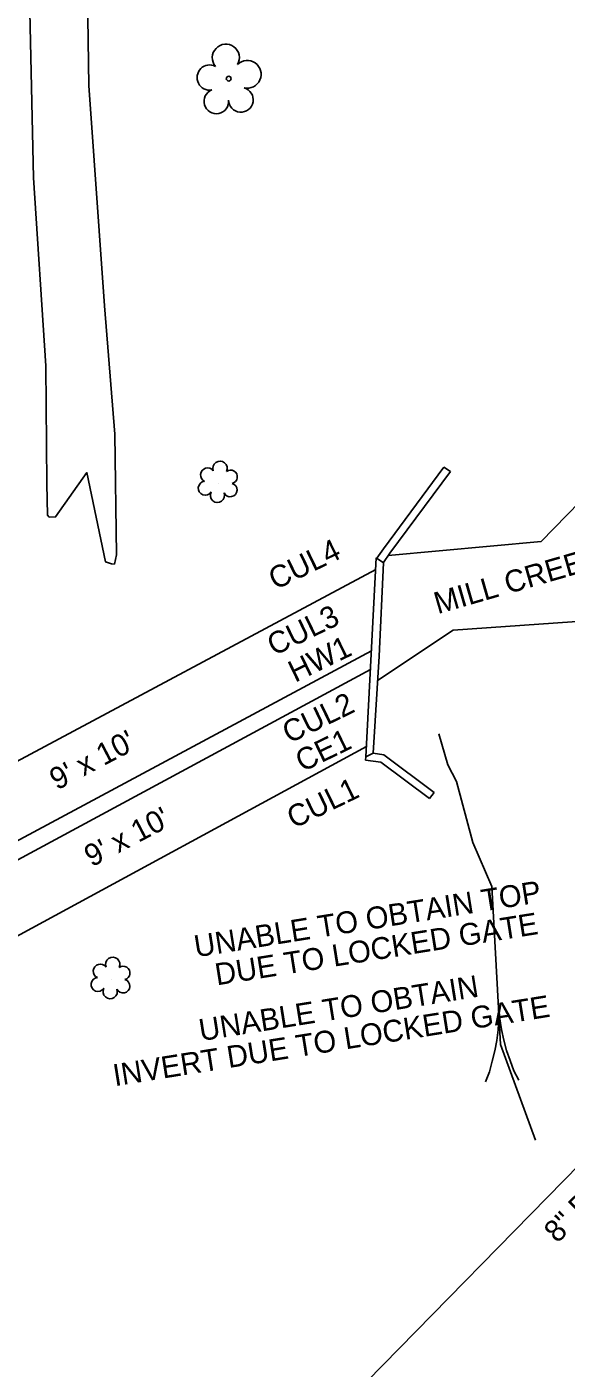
# Model space of a CAD drawing. Extents: x 1645945 to 2447332, y 713118 to 970361.
# Drawn here: x 1646352.4 to 1646426.4, y 969166.9 to 969350.8 of the extents above; entities that cross this region are included whole.
import ezdxf

# ---------------------------------------------------------------- set-up
doc = ezdxf.new("R2010")
doc.units = 0
for name, color, linetype in [('Exist Hydro Jurisdictional Stream or Body of Water', 7, 'Continuous'), ('Exist Hydro Stream Flow Arrow CELL', 7, 'Continuous'), ('Exist Hydro Stream or Body of Water', 7, 'Continuous'), ('Exist Hydro Stream or Body of Water Text', 7, 'Continuous'), ('Exist Roads EOP', 7, 'Continuous'), ('Exist Structure Major Box Culvert or Tunnel Topo', 7, 'Continuous'), ('Exist Structure Major Box Culvert or Tunnel Topo Text', 7, 'Continuous'), ('Exist Structure Major Bridge WW', 7, 'Continuous'), ('Exist Structure Major Bridge WW Text', 7, 'Continuous'), ('Exist Utilities Sanitary Sewer Manhole Top Elevation', 7, 'Continuous'), ('Exist Utilities Sanitary Sewer UG Line', 7, 'Continuous'), ('Exist Utilities Sanitary Sewer UG Line Invert Elevation', 7, 'Continuous'), ('Exist Utilities Sanitary Sewer UG Line Text', 7, 'Continuous'), ('Exist Vegetation Shrub CELL', 7, 'Continuous'), ('Exist Vegetation Tree CELL', 7, 'Continuous'), ('Exist Vegetation Woods Line', 7, 'Continuous')]:
    doc.layers.add(name, color=color, linetype=linetype)

msp = doc.modelspace()

# ---------------------------------------------------------------- linework, layer by layer
at = {"layer": 'Exist Hydro Jurisdictional Stream or Body of Water'}
for points in [[(1646401.99, 969278.32), (1646423.01, 969280.26), (1646437.23, 969294.85), (1646457.43, 969315.9), (1646475.67, 969321.15), (1646485.57, 969322.27), (1646516.72, 969316.81), (1646532.37, 969313.33), (1646530.94, 969311.42), (1646556.57, 969305.09), (1646573.02, 969284.42), (1646579.39, 969286.45), (1646594.79, 969278.15), (1646612.91, 969277.12), (1646627.6, 969287.18), (1646621.62, 969307.78), (1646603.14, 969335.3), (1646602.11, 969357.23), (1646611.25, 969365.23), (1646620.99, 969368.56)], [(1646400.54, 969261.2), (1646410.92, 969268.12), (1646429.85, 969269.44), (1646447.81, 969287.37), (1646463.87, 969298.89), (1646476.09, 969310.23), (1646484.82, 969314.47), (1646502.05, 969312.4), (1646515.09, 969307.54), (1646531.96, 969305.19), (1646552.01, 969296.08), (1646566.89, 969282.54), (1646572.86, 969281.73), (1646573.04, 969276.65), (1646593.17, 969267.28), (1646615.05, 969269.41), (1646633.01, 969284.64), (1646632.51, 969310.52), (1646631.26, 969330.1), (1646614.63, 969342.37), (1646608.88, 969351.32), (1646612.08, 969360.76), (1646623.03, 969361.26)]]:
    msp.add_lwpolyline(points, dxfattribs=at)
at = {"layer": 'Exist Hydro Stream Flow Arrow CELL'}
msp.add_line((1646417.4, 969211.26), (1646417.4, 969211.26), dxfattribs=at)
for points in [[(1646415.34, 969206.16), (1646415.88, 969207.52), (1646416.28, 969208.97), (1646416.65, 969210.4), (1646416.9, 969211.82), (1646417.08, 969213.29), (1646417.17, 969214.79), (1646417.18, 969216.25)], [(1646419.91, 969206.36), (1646419.25, 969207.67), (1646418.73, 969209.07), (1646418.23, 969210.47), (1646417.85, 969211.86), (1646417.55, 969213.31), (1646417.32, 969214.79), (1646417.18, 969216.25)]]:
    msp.add_lwpolyline(points, dxfattribs=at)
at = {"layer": 'Exist Hydro Stream or Body of Water'}
msp.add_lwpolyline([(1646422.22, 969198.15), (1646417.4, 969211.26), (1646416.21, 969232.96), (1646413.62, 969238.97), (1646411.35, 969247.33), (1646410.16, 969249.65), (1646408.93, 969253.86)], dxfattribs=at)
at = {"layer": 'Exist Roads EOP'}
msp.add_spline([(1646379.88, 969432.02), (1646359.09, 969426.37), (1646353.34, 969423.7), (1646346.05, 969418.75), (1646333.89, 969406.7), (1646326.81, 969393.02), (1646325.09, 969385.45), (1646325.5, 969379.16), (1646330.03, 969336.13), (1646333.52, 969294.46), (1646334.18, 969250.57), (1646332.28, 969209.59), (1646328.48, 969164.09), (1646321.21, 969122.91)], degree=3, dxfattribs=at)
at = {"layer": 'Exist Structure Major Box Culvert or Tunnel Topo'}
for p, q in [((1646246.39, 969194.17), (1646400.28, 969276.43)), ((1646245.55, 969182.6), (1646399.69, 969265.26)), ((1646399.55, 969262.69), (1646245.35, 969179.57)), ((1646244.67, 969168.45), (1646399, 969252.16))]:
    msp.add_line(p, q, dxfattribs=at)
at = {"layer": 'Exist Structure Major Bridge WW'}
for p, q in [((1646409.62, 969290.47), (1646410.53, 969289.87)), ((1646398.92, 969250.71), (1646400.36, 969278)), ((1646398.9, 969250.25), (1646398.92, 969250.71)), ((1646400.98, 969249.99), (1646398.9, 969250.25)), ((1646401.4, 969251.02), (1646399.93, 969251.21)), ((1646407.64, 969244.99), (1646400.98, 969249.99)), ((1646408.29, 969245.85), (1646401.4, 969251.02)), ((1646408.29, 969245.85), (1646407.64, 969244.99))]:
    msp.add_line(p, q, dxfattribs=at)
for points in [[(1646400.42, 969277.95), (1646401.33, 969279.25), (1646409.62, 969290.47)], [(1646401.34, 969277.37), (1646402.24, 969278.66), (1646410.53, 969289.87)], [(1646398.92, 969250.71), (1646399.93, 969251.21), (1646400.74, 969264.52), (1646401.37, 969277.35), (1646400.36, 969278)]]:
    msp.add_lwpolyline(points, dxfattribs=at)
at = {"layer": 'Exist Utilities Sanitary Sewer UG Line'}
msp.add_line((1646382.01, 969147.69), (1646479.6, 969247.22), dxfattribs=at)
at = {"layer": 'Exist Vegetation Shrub CELL'}
for p, q in [((1646378.68, 969288.26), (1646378.68, 969288.26)), ((1646363.96, 969220.2), (1646363.96, 969220.2))]:
    msp.add_line(p, q, dxfattribs=at)
for centre, radius, start, end in [((1646377.2, 969289.39), 0.968, 35.8908, 245.4216), ((1646378.91, 969290.3), 0.99, 334.8391, 200.4717), ((1646376.88, 969287.56), 0.955, 95.1099, 327.9534), ((1646380.36, 969289.13), 0.929, 284.4567, 126.0861), ((1646378.56, 969286.58), 0.984, 151.2797, 21.387), ((1646380.32, 969287.33), 0.937, 204.9913, 73.4601), ((1646362.48, 969221.33), 0.968, 35.8908, 245.4216), ((1646364.19, 969222.24), 0.99, 334.8391, 200.4717), ((1646362.16, 969219.5), 0.955, 95.1099, 327.9534), ((1646365.63, 969221.07), 0.929, 284.4567, 126.0861), ((1646363.83, 969218.52), 0.984, 151.2797, 21.387), ((1646365.6, 969219.27), 0.937, 204.9913, 73.4601)]:
    msp.add_arc(centre, radius, start, end, dxfattribs=at)
at = {"layer": 'Exist Vegetation Tree CELL'}
msp.add_line((1646380.1, 969343.74), (1646380.1, 969343.74), dxfattribs=at)
msp.add_circle((1646380.1, 969343.74), 0.326, dxfattribs=at)
for centre, radius, start, end in [((1646379.71, 969346.61), 1.86, 330.1651, 219.7134), ((1646377.49, 969343.89), 1.73, 62.6636, 279.3457), ((1646382.65, 969344.33), 1.9, 257.1011, 134.1999), ((1646378.4, 969340.62), 1.69, 111.5671, 6.231), ((1646381.77, 969340.84), 1.7, 181.2822, 74.56)]:
    msp.add_arc(centre, radius, start, end, dxfattribs=at)
at = {"layer": 'Exist Vegetation Woods Line'}
msp.add_lwpolyline([(1646360.59, 969364.52), (1646360.91, 969342.79), (1646363.07, 969312.57), (1646364.46, 969294.96), (1646364.72, 969278.41), (1646364.42, 969277.15), (1646364.02, 969277.18), (1646363.18, 969277.49), (1646360.65, 969289.7), (1646356.35, 969283.62), (1646355.46, 969283.59), (1646355.25, 969283.86), (1646355.12, 969288.18), (1646355.02, 969304.34), (1646353.33, 969330.13), (1646352.34, 969373.68)], dxfattribs=at)

# ---------------------------------------------------------------- texts
at = {"layer": 'Exist Hydro Stream or Body of Water Text'}
msp.add_text('MILL CREEK', height=3, rotation=16.0706, dxfattribs=at).set_placement((1646408.79, 969270.28))
at = {"layer": 'Exist Structure Major Box Culvert or Tunnel Topo Text'}
for p in [(1646356.53, 969246.09), (1646361.29, 969235.55)]:
    msp.add_text("9' x 10'", height=3, rotation=27.6892, dxfattribs=at).set_placement(p)
at = {"layer": 'Exist Structure Major Bridge WW Text'}
for s, p in [('CUL4', (1646386.51, 969273.57)), ('CUL3', (1646386.32, 969264.52)), ('HW1 ', (1646389.22, 969260.86)), ('CUL2', (1646388.4, 969252.5)), ('CE1', (1646390.2, 969248.59)), ('CUL1', (1646389.03, 969240.82))]:
    msp.add_text(s, height=3, rotation=25.8932, dxfattribs=at).set_placement(p)
at = {"layer": 'Exist Utilities Sanitary Sewer Manhole Top Elevation'}
for s, p in [('UNABLE TO OBTAIN TOP', (1646375.61, 969223.22)), ('DUE TO LOCKED GATE', (1646378.47, 969219.37))]:
    msp.add_text(s, height=3, rotation=9.0698, dxfattribs=at).set_placement(p)
at = {"layer": 'Exist Utilities Sanitary Sewer UG Line Invert Elevation'}
for s, p in [('UNABLE TO OBTAIN', (1646376.27, 969211.73)), ('INVERT DUE TO LOCKED GATE', (1646364.47, 969205.54))]:
    msp.add_text(s, height=3, rotation=9.0698, dxfattribs=at).set_placement(p)
at = {"layer": 'Exist Utilities Sanitary Sewer UG Line Text'}
msp.add_text('8" DIP', height=3, rotation=45.5644, dxfattribs=at).set_placement((1646425.22, 969183.91))

doc.saveas('drawing.dxf')
